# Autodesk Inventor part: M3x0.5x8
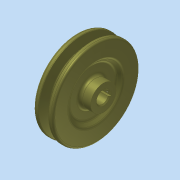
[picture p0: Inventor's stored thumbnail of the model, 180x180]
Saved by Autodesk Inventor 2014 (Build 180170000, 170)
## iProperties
Company: 한국ATC센터
Created: 2009-02
Part Number: M3x0.5x8
Document SubType Name: Modeling
Designer: KYOUNG IL JANG
Density: 7.25 g/cm^3
Mass: 594.644 g
Surface Area: 210.328 cm^2
Volume: 82.0198 cm^3
Material: 주철
Vendor: CBT Solutions
Appearance: 티타늄
Author: KYOUNG IL JANG
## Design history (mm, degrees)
sketch "스케치1"
  geometry: L1 (-13, 0)-(13, 0); L2 (-13, 0)-(-13, 12.5); L3 (-13, 12.5)-(-9, 12.5); L4 (-9, 12.5)-(-9, 23); L5 (-9, 23)-(-13, 27); L6 (-13, 27)-(-13, 42.7); L7 (-13, 42.7)-(-8.325, 42.7); L8 (-8.325, 42.7)-(-5.574, 33.7); L9 (-5.574, 33.7)-(-1.426, 33.7); L10 (-1.426, 33.7)-(1.325, 42.7); L11 (1.325, 42.7)-(6, 42.7); L12 (6, 42.7)-(6, 27); L13 (6, 27)-(2, 23); L14 (2, 23)-(2, 12.5); L15 (2, 12.5)-(13, 12.5); L16 (13, 12.5)-(13, 0); L17 (-7.5, 40)-(0.5, 40); 2 further points
  constraints: 34 end point, 6 parallel, 5 collinear, 5 equal length, 4 perpendicular, 2 point on line, 1 coincident, 1 horizontal, 1 midpoint
  dimensions: "d0" = 26 distance of L1.start L1.end; "d1" = 2.7 distance between parallel lines of L7 L17; "d2" = 6.3 distance between parallel lines of L9 L17; "d3" = 8 distance of L17.start L17.end; "d4" = 34 deg angle of L10 L8; "d5" = 19 distance between parallel lines of L12 L6; "d7" = 25 diameter of L15 L1; "d8" = 46 diameter of L13.end L1; "d9" = 54 diameter of L12.end L1; "d10" = 4 distance between parallel lines of L2 L4; "d11" = 80 diameter of L17 L1
revolve "회전1" sketch "스케치1" stored, may be unused: angle "d12" = 90 deg
sketch "스케치2"
  geometry: L1 (-2, 5.657)-(-2, 7.8); L2 (-2, 7.8)-(2, 7.8); L3 (2, 7.8)-(2, 5.657); A1 r 6 centre (0, 0) between (-2, 5.657) and (2, 5.657); 1 further point
  constraints: 6 end point, 2 parallel, 2 point on circle, 1 centre point, 1 coincident, 1 perpendicular, 1 vertical
  dimensions: "d13" = 12 diameter of A1; "d14" = 13.8 dimension on A1 L2; "d15" = 4 distance of L1.end L2.end
extrude "돌출1" cut sketch "스케치2" stored distance "d16" = 10; taper "d17" = 0 deg
node "작업 평면1"
sketch "스케치3"
  geometry: L1 (-5.5, 12.5)-(-5.5, -12.5) reference; 3 further points
  constraints: 1 horizontal alignment, 1 midpoint
  dimensions: "d18" = 4 distance from line of point (-1.5, 0) L1
hole "구멍1" sketch "스케치3" at (-1.5, 0) diameter "d19" = 2.459; stored, may be unused: countersink angle "d23" = 90 deg, drill point angle "d25" = 118 deg; dims "d20" = 6, "d21" = 4, "d22" = 2, "d24" = 8
fillet "모깎기1" dims "d26" = 2, "d27" = 0.5, "d28" = 1, "d29" = 3
chamfer "모따기1" distance "d30" = 1; stored, may be unused: second distance "d31" = 2, angle "d32" = 45 deg
node "솔리드1"
